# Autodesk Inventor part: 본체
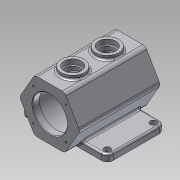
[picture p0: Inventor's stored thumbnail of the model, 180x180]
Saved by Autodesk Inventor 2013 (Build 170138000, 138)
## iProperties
Created: 2021-06
Part Number: 본체
Material: 알루미늄 6061
Document SubType Name: Modeling
Designer: hana-cad17
Density: 2.71 g/cm^3
Mass: 1497.51 g
Surface Area: 1102.42 cm^2
Volume: 552.587 cm^3
Author: hana-cad17
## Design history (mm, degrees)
sketch "스케치1" dims "d0" = 105
  geometry: L1 (26.25, 45.466)-(52.5, 0); L2 (52.5, 0)-(26.25, -45.466); L3 (26.25, -45.466)-(-26.25, -45.466); L4 (-26.25, -45.466)-(-52.5, 0); L5 (-52.5, 0)-(-26.25, 45.466); L6 (-26.25, 45.466)-(26.25, 45.466); L7 (73.5, 0)-(-73.5, 0) reference; L8 (0, -73.5)-(0, 73.5) reference; 3 further points
  constraints: 12 end point, 2 coincident, 1 horizontal alignment, 1 point on line, 15 other
extrude "돌출1" new body sketch "스케치1" stored distance "d2" = 140; taper "d3" = 0 deg
node "작업 평면1"
sketch "스케치2"
  geometry: L1 (-105, 0)-(105, 0) reference; L2 (0, -98)-(0, 98) reference; L3 (-75, 55)-(75, 55); L4 (75, 55)-(75, -45); L5 (75, -45)-(-75, -45); L6 (-75, -45)-(-75, 55); L7 (-75, 55)-(75, -45); L8 (75, 55)-(-75, -45); L9 (-26.25, -70)-(-26.25, 70) reference; L10 (-52.5, 70)-(-26.25, 70) reference; L11 (-52.5, 70)-(-52.5, -70) reference; L12 (-26.25, -70)-(-52.5, -70) reference; L13 (26.25, 70)-(26.25, -70) reference; L14 (-26.25, 70)-(26.25, 70) reference; L15 (-26.25, -70)-(-26.25, 70) reference; L16 (26.25, -70)-(-26.25, -70) reference; L17 (52.5, 70)-(52.5, -70) reference; L18 (26.25, 70)-(52.5, 70) reference; L19 (26.25, 70)-(26.25, -70) reference; L20 (52.5, -70)-(26.25, -70) reference; 2 further points
  constraints: 12 end point, 2 midpoint, 2 parallel, 1 horizontal, 1 perpendicular, 1 point on line
  dimensions: "d9" = 25 distance between parallel lines of L5 L16; "d10" = 100 distance of L5.end L3.start; "d11" = 150 distance of L3.start L3.end
extrude "돌출2" join sketch "스케치2" distance "d12" = 12; taper "d13" = 0 deg
fillet "모깎기1" dims "d14" = 10
sketch "스케치3"
  geometry: C1 r 5.5 at (-65, 45); C2 r 5.5 at (-65, -35); C3 r 5.5 at (65, -35); C4 r 5.5 at (65, 45); A1 r 10 centre (65, 45) between (75, 45) and (65, 55) reference; A2 r 10 centre (-65, 45) between (-65, 55) and (-75, 45) reference; A3 r 10 centre (-65, -35) between (-75, -35) and (-65, -45) reference; A4 r 10 centre (65, -35) between (65, -45) and (75, -35) reference; 1 further point
  constraints: 4 centre point, 4 coincident, 3 equal radius
  dimensions: "d15" = 11 diameter of C1
extrude "돌출3" cut sketch "스케치3" stored distance "d17" = 12; taper "d18" = 0 deg
sketch "스케치4"
  geometry: C1 r 30 at (0, 0); 1 further point
  constraints: 1 centre point, 1 coincident
  dimensions: "d19" = 60 diameter of C1
extrude "돌출4" cut sketch "스케치4" distance "d21" = 12; taper "d22" = 0 deg
sketch "스케치5"
  geometry: C1 r 30 at (0, 0) reference; C2 r 37.5 at (0, 0)
  constraints: 1 centre point, 1 coincident
  dimensions: "d23" = 75 diameter of C2
extrude "돌출5" cut sketch "스케치5" distance "d25" = 116; taper "d26" = 0 deg
sketch "스케치6"
  geometry: C1 r 37.5 at (0, 0) reference; C2 r 30 at (0, 0)
  constraints: 1 centre point, 1 coincident
  dimensions: "d27" = 60 diameter of C2
extrude "돌출6" cut sketch "스케치6" distance "d29" = 12; taper "d30" = 0 deg
node "작업 평면2"
sketch "스케치10"
  geometry: L1 (-105, 0)-(105, 0) reference; L2 (0, -98)-(0, 98) reference; L3 (-26.25, -45)-(26.25, -45) reference; L4 (26.25, 70)-(26.25, -70) reference; L5 (-26.25, 70)-(26.25, 70) reference; L6 (-26.25, -70)-(-26.25, 70) reference; L7 (26.25, -70)-(-26.25, -70) reference; C1 r 20 at (0, -30); C2 r 20 at (0, 30); 1 further point
  constraints: 2 centre point, 2 point on line
  dimensions: "d61" = 40 diameter of C1; "d63" = 40 diameter of C2; "d64" = 40 distance from line of L7 C1.centre; "d65" = 60 distance of C1.centre C2.centre
extrude "돌출7" join sketch "스케치10" stored distance "d66" = 11; taper "d67" = 0 deg
sketch "스케치11"
  geometry: C1 r 20 at (0, 0) reference; C2 r 15 at (0, 0); C3 r 20 at (0, 60) reference; C4 r 15 at (0, 60); 1 further point
  constraints: 2 centre point, 2 coincident
  dimensions: "d68" = 30 diameter of C2; "d70" = 30 diameter of C4
extrude "돌출8" cut sketch "스케치11" distance "d71" = 8; taper "d72" = 0 deg
sketch "스케치12"
  geometry: C1 r 15 at (0, 0) reference; C2 r 15 at (0, 60) reference; C3 r 12.5 at (0, 0); C4 r 12.5 at (0, 60); 1 further point
  constraints: 2 centre point, 2 coincident
  dimensions: "d73" = 25 diameter of C3; "d75" = 25 diameter of C4
extrude "돌출9" cut sketch "스케치12" stored distance "d76" = 0; taper "d77" = 0 deg
sketch "스케치13"
  geometry: L1 (-105, 0)-(105, 0) reference; L2 (0, -70.5)-(0, 73) reference; L3 (0, 0)-(-59.378, 59.378); L4 (0, 0)-(50.749, 50.749); L5 (0, 0)-(-77.756, -77.756); L6 (0, 0)-(69.454, -69.454); C1 r 30 at (0, 0) reference; A1 r 40 centre (0, 0) between (-28.284, 28.284) and (28.284, 28.284); 2 further points
  constraints: 8 end point, 4 point on circle, 4 point on line, 1 centre point, 1 coincident
  dimensions: "d78" = 80 diameter of A1; "d80" = 45 deg angle of L2 L3; "d82" = 45 deg angle of L2 L5; "d84" = 45 deg angle of L2 L6; "d86" = 45 deg angle of L4 L2
hole "구멍3" sketch "스케치13" at (-28.284, 28.284), (28.284, 28.284), (28.284, -28.284), (-28.284, -28.284) diameter "d88" = 3.242; stored, may be unused: countersink angle "d92" = 90 deg, drill point angle "d94" = 118 deg; dims "d89" = 8, "d90" = 4, "d91" = 2, "d93" = 10
fillet "모깎기2" dims "d95" = 8, "d96" = 3, "d113" = 5
chamfer "모따기1" distance "d97" = 1; stored, may be unused: second distance "d98" = 2, angle "d99" = 45 deg
sketch "스케치14"
  geometry: L1 (-75, 45)-(-75, -35) reference; L2 (-65, -45)-(-32.293, -45) reference; 2 further points
  constraints: 1 other
  dimensions: "d100" = 14 distance from line of point (-61, 5) L1; "d101" = 50 distance from line of L2 point (-61, 5)
feature "엠보싱1" sketch "스케치14" dims "d0" = 105, "d102" = 0.5, "d103" = 0
sketch "스케치15"
  geometry: L1 (-105, 0)-(105, 0) reference; L2 (0, 70.5)-(0, -73) reference; C1 r 31 at (0, 0) reference; A1 r 40 centre (0, 0) between (0, -40) and (40, 0); 2 further points
  constraints: 4 point on circle, 4 point on line, 1 centre point, 1 coincident
  dimensions: "d104" = 80 diameter of A1
hole "구멍4" sketch "스케치15" at (0, -40), (40, 0), (0, 40), (-40, 0) diameter "d106" = 3.242; stored, may be unused: countersink angle "d110" = 90 deg, drill point angle "d112" = 118 deg; dims "d107" = 8, "d108" = 4, "d109" = 2, "d111" = 10
node "솔리드1"
node "투영된 루프3"
node "투영된 루프4"
node "투영된 루프5"
node "투영된 루프7"
node "투영된 루프8"
node "투영된 루프9"
other parameters: "d60" = 52.5
